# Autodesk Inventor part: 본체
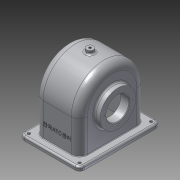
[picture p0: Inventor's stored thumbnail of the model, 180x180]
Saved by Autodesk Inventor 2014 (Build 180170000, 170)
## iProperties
Created: 2016-01
Part Number: 본체
Material: Aluminum 6061
Document SubType Name: Modeling
Designer: user
Density: 2.71 g/cm^3
Appearance: Aluminum - Flat
Mass: 847.204 g
Surface Area: 1011.63 cm^2
Volume: 312.621 cm^3
Author: user
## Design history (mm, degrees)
sketch "Sketch1"
  geometry: L1 (-52, -70)-(52, -70); L2 (52, -70)-(52, 70); L3 (52, 70)-(-52, 70); L4 (-52, 70)-(-52, -70); L5 (-52, -70)-(52, 70); L6 (52, -70)-(-52, 70); 5 further points
  constraints: 12 end point, 6 midpoint, 1 horizontal alignment, 1 vertical alignment
  dimensions: "d0" = 104 distance between parallel lines of L2 L4; "d1" = 140 distance between parallel lines of L1 L3
extrude "Extrusion1" new body sketch "Sketch1" distance "d2" = 7; taper "d3" = 0 deg
sketch "Sketch2"
  geometry: L1 (-52, -70)-(52, -70) reference; L2 (52, -70)-(52, 70) reference; L3 (52, 70)-(-52, 70) reference; L4 (-52, 70)-(-52, -70) reference; L5 (-44, 62)-(44, 62); L6 (44, 62)-(44, -62); L7 (44, -62)-(-44, -62); L8 (-44, -62)-(-44, 62); C1 r 2.5 at (-44, 62); C2 r 2.5 at (44, 62); C3 r 2.5 at (-44, -62); C4 r 2.5 at (44, -62); 1 further point
  constraints: 8 end point, 4 centre point, 4 coincident, 3 equal radius, 3 other
  dimensions: "d4" = 8 distance between parallel lines of L8 L4; "d5" = 5 diameter of C1
extrude "Extrusion2" cut sketch "Sketch2" stored distance "d6" = 7; taper "d7" = 0 deg
sketch "Sketch3"
  geometry: L1 (-38.5, -57)-(38.5, -57); L2 (38.5, -57)-(38.5, 57); L3 (38.5, 57)-(-38.5, 57); L4 (-38.5, 57)-(-38.5, -57); L5 (-38.5, -57)-(38.5, 57); L6 (38.5, -57)-(-38.5, 57); 5 further points
  constraints: 12 end point, 6 midpoint, 1 horizontal alignment, 1 vertical alignment
  dimensions: "d8" = 114 distance between parallel lines of L3 L1; "d9" = 77 distance between parallel lines of L2 L4
extrude "Extrusion3" join sketch "Sketch3" distance "d10" = 57; taper "d11" = 0 deg
sketch "Sketch4"
  geometry: L1 (0, 114)-(-57, 114) reference; L2 (-57, 0)-(-57, 114) reference; L3 (-57, 0)-(-57, 114); A1 r 57 centre (-57, 57) between (-57, 114) and (-57, 0); 1 further point
  constraints: 3 end point, 3 point on circle, 1 centre point, 1 midpoint, 1 point on line
extrude "Extrusion4" join sketch "Sketch4" distance "d12" = 77; taper "d13" = 0 deg
sketch "Sketch6"
  geometry: L1 (7, -13)-(7, 127) reference; L2 (-53, -13)-(-53, 127); L3 (7, 57)-(-53, 57); C1 r 31 at (-53, 57)
  constraints: 4 end point, 1 centre point, 1 coincident, 1 midpoint, 1 parallel
  dimensions: "d26" = 60 distance between parallel lines of L1 L2; "d27" = 62 diameter of C1
extrude "Extrusion5" join sketch "Sketch6" distance "d28" = 10; taper "d29" = 0 deg
workplane "Work Plane1"
sketch "Sketch7"
  geometry: C1 r 6 at (0, 0); 1 further point
  constraints: 1 centre point, 1 coincident
  dimensions: "d31" = 12 diameter of C1
extrude "Extrusion6" join sketch "Sketch7" stored distance "d32" = 6; taper "d33" = 0 deg
sketch "Sketch11"
  geometry: L1 (57, 7)-(-57, 7) reference; L2 (57, 7)-(57, 64) reference; L3 (-57, 7)-(-57, 64) reference; L4 (51, 64)-(51, 0); L5 (-51, 0)-(-51, 64); L6 (70, 0)-(-70, 0) reference; L7 (-70, 0)-(-70, 7) reference; L8 (70, 7)-(-70, 7) reference; L9 (70, 0)-(70, 7) reference; L10 (-51, 0)-(51, 0); C1 r 31 at (0, 60) reference; A1 r 57 centre (0, 64) between (57, 64) and (-57, 64) reference; A2 r 51 centre (0, 64) between (51, 64) and (-51, 64); 1 further point
  constraints: 6 end point, 2 point on circle, 2 point on line, 1 centre point
  dimensions: "d62" = 6 radial gap between concentric circles of A2 A1; "d63" = 102 distance between parallel lines of L4 L5; "d64" = 64 distance from line of L6 L5.end
extrude "Extrusion7" cut sketch "Sketch11" stored distance "d65" = 67; taper "d66" = 0 deg
sketch "Sketch12"
  geometry: L1 (38.5, 7)-(38.5, 64) reference; L2 (33.5, 115)-(-33.5, 115) reference; L3 (33.5, 64)-(33.5, 115) reference; L4 (-33.5, 115)-(-33.5, 64) reference; L5 (-33.5, 0)-(-33.5, 64) reference; L6 (-52, 0)-(52, 0) reference; L7 (-52, 60)-(52, 60); L8 (19.5, 60)-(19.5, 88); L9 (19.5, 88)-(33.5, 99.747); L10 (33.5, 99.747)-(33.5, 60); 1 further point
  constraints: 8 end point, 3 point on line, 1 parallel
  dimensions: "d67" = 60 distance between parallel lines of L6 L7; "d68" = 50 deg angle of L8 L9; "d70" = 56 diameter of L8.end L7
revolve "Revolution2" sketch "Sketch12" stored, may be unused: angle "d71" = 90 deg
sketch "Sketch13"
  geometry: L1 (35.5, 94.899)-(38.5, 97.416); L2 (35.5, 80)-(35.5, 94.899); L3 (19.5, 32)-(19.5, 88) reference; L4 (-33.5, 0)-(33.5, 0) reference; L5 (-33.5, 60)-(38.5, 60); L6 (38.5, 7)-(38.5, 64) reference; L7 (38.5, 60)-(38.5, 80); L8 (19.5, 88)-(33.5, 99.747) reference; L9 (35.5, 80)-(19.5, 80); L10 (38.5, 97.416)-(38.5, 80); L11 (19.5, 80)-(19.5, 60); 1 further point
  constraints: 14 end point, 4 point on line, 1 midpoint, 1 parallel
  dimensions: "d76" = 60 distance between parallel lines of L4 L5; "d77" = 40 diameter of L9 L5
revolve "Revolution3" sketch "Sketch13" stored, may be unused: angle "d78" = 90 deg
hole "Hole1" diameter "d81" = 40; stored, may be unused: countersink angle "d85" = 90 deg, drill point angle "d87" = 0 deg; dims "d79" = 10, "d80" = 10, "d82" = 6, "d83" = 4, "d84" = 2, "d86" = 8
sketch "Sketch14" dims "d88" = 48
  geometry: L1 (0, 0)-(-24, 0); C1 r 31 at (0, 0) reference; 2 further points
  constraints: 2 coincident, 2 end point, 1 horizontal alignment, 2 other
hole "Hole2" sketch "Sketch14" at (-24, 0) diameter "d89" = 2.459; stored, may be unused: countersink angle "d93" = 90 deg, drill point angle "d95" = 120 deg; dims "d90" = 6, "d91" = 4, "d92" = 2, "d94" = 8
pattern_circular "Circular Pattern1" dims angle "d97" = 360 deg
sketch "Sketch15" dims "d99" = 56
  geometry: L1 (0.71, 0)-(28, 0); C1 r 34.899 at (0, 0) reference; 3 further points
  constraints: 2 coincident, 2 end point, 1 horizontal alignment, 2 other
hole "Hole3" sketch "Sketch15" at (28, 0) diameter "d100" = 2.459; stored, may be unused: countersink angle "d104" = 90 deg, drill point angle "d106" = 120 deg; dims "d101" = 7, "d102" = 4, "d103" = 2, "d105" = 9
pattern_circular "Circular Pattern2" dims angle "d108" = 360 deg
hole "Hole4" diameter "d112" = 4.134; stored, may be unused: countersink angle "d116" = 90 deg, drill point angle "d118" = 120 deg; dims "d110" = 10, "d111" = 10, "d113" = 7, "d114" = 4, "d115" = 2, "d117" = 9
sketch "Sketch16"
  geometry: L1 (-13.5, -7)-(90.5, -7) reference; L2 (-13.5, 23)-(90.5, 23); L3 (38.5, -7)-(38.5, 37.901); 2 further points
  constraints: 4 end point, 1 coincident, 1 midpoint, 1 parallel, 1 point on line, 1 other
  dimensions: "d119" = 30 distance between parallel lines of L1 L2
emboss "Emboss1" sketch "Sketch16" dims "d0" = 104, "d1" = 140, "d120" = 0.5, "d121" = 0
fillet "Fillet1" dims "d122" = 8
fillet "Fillet2" dims "d123" = 3
chamfer "Chamfer1" distance "d126" = 1; stored, may be unused: second distance "d127" = 2, angle "d128" = 45 deg
fillet "Fillet5" dims "d129" = 3
fillet "Fillet6" dims "d130" = 3
fillet "Fillet7" dims "d131" = 3
fillet "Fillet8" dims "d132" = 9
fillet "Fillet9" dims "d133" = 14
fillet "Fillet10" dims "d134" = 1
body "Solid1"
node "Projected Loop1"
node "Projected Loop2"
other parameters: "d30" = 127, "d51" = 50 deg, "d56" = 50 deg
